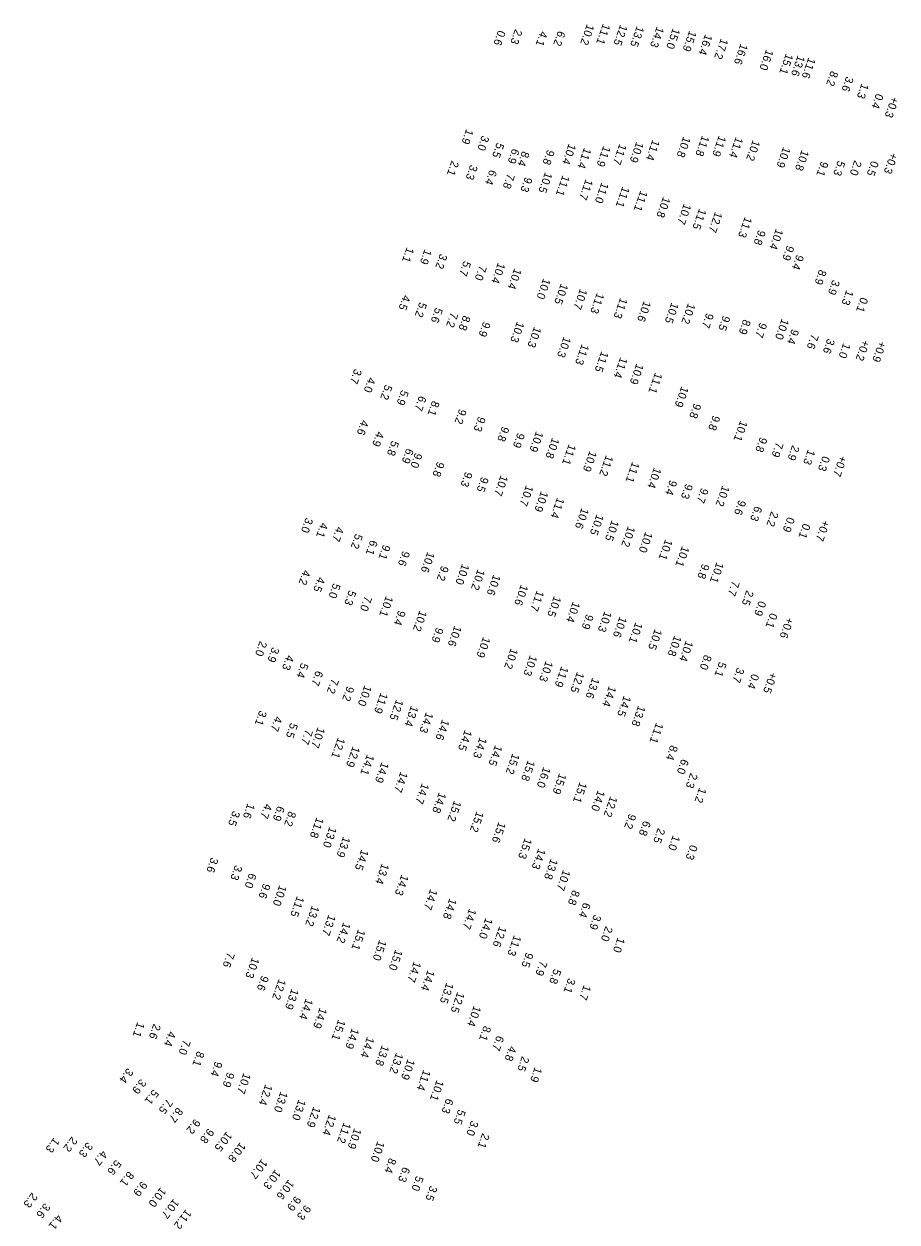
# Model space of a CAD drawing. Extents: x 815385 to 820851, y 582449 to 604245.
# Drawn here: x 817864 to 818409, y 602062 to 602810 of the extents above; entities that cross this region are included whole.
import ezdxf

# ---------------------------------------------------------------- set-up
doc = ezdxf.new("R2010")
doc.units = 0
doc.layers.add('V-TOPO-SOUN-022409', color=7, linetype='Continuous')

msp = doc.modelspace()

# ---------------------------------------------------------------- texts
at = {"layer": 'V-TOPO-SOUN-022409'}
for s, rotation, p in [('10.2 ', 250.57, (818215.18, 602810.48)), ('11.1 ', 250.57, (818225.18, 602810.79)), ('12.5 ', 250.57, (818235.95, 602810.16)), ('0.6', 250.57, (818159.79, 602806.7)), ('2.3', 250.57, (818170.28, 602807.36)), ('4.1', 250.57, (818186.12, 602806.2)), ('6.2', 250.57, (818197.11, 602806.34)), ('13.5 ', 250.57, (818246.32, 602809.31)), ('14.3 ', 250.57, (818258.75, 602808.9)), ('15.0 ', 250.57, (818268.81, 602807.99)), ('15.9 ', 250.57, (818279.06, 602806.41)), ('16.4 ', 250.57, (818288.97, 602804.18)), ('17.2 ', 250.57, (818298.82, 602801.57)), ('16.6 ', 250.57, (818311.09, 602798.29)), ('16.0 ', 250.57, (818327.04, 602794.69)), ('15.1 ', 250.57, (818339.41, 602792.1)), ('13.6 ', 250.57, (818346.74, 602791)), ('11.6 ', 250.57, (818353.41, 602789.58)), ('8.2', 250.57, (818367.48, 602781.33)), ('3.6', 250.57, (818377.07, 602777.89)), ('1.3', 250.57, (818386.62, 602773.44)), ('0.4', 250.57, (818395.7, 602767.21)), ('+0.3 ', 250.57, (818405.31, 602765.25)), ('1.9', 250.57, (818139.8, 602745)), ('3.0', 250.57, (818149.64, 602740.98)), ('5.5', 250.57, (818158.93, 602736.51)), ('10.4 ', 250.57, (818203.82, 602735.82)), ('11.7 ', 250.57, (818235.49, 602735.71)), ('10.9 ', 250.57, (818246.02, 602737.02)), ('11.4 ', 250.57, (818256.12, 602738.3)), ('10.8 ', 250.57, (818275.35, 602740.28)), ('11.8 ', 250.57, (818287.07, 602740.98)), ('11.9 ', 250.57, (818297.53, 602740.83)), ('11.4 ', 250.57, (818308.12, 602740.01)), ('10.2 ', 250.57, (818318.74, 602738.12)), ('6.9', 250.57, (818168.6, 602732.83)), ('8.4', 250.57, (818174.75, 602731.23)), ('9.8', 250.57, (818190.43, 602732.12)), ('11.4 ', 250.57, (818213.39, 602733.31)), ('11.9 ', 250.57, (818225.38, 602734.45)), ('10.9 ', 250.57, (818337.68, 602733.84)), ('10.8 ', 250.57, (818349.24, 602731.93)), ('+0.3 ', 250.57, (818404.69, 602730.21)), ('2.1', 250.57, (818130.69, 602725.27)), ('3.3', 250.57, (818142.41, 602722.72)), ('9.1', 250.57, (818361.36, 602724.91)), ('5.3', 250.57, (818371.84, 602725.28)), ('2.0', 250.57, (818382.17, 602725.47)), ('0.5', 250.57, (818392.74, 602725.2)), ('6.4', 250.57, (818154.44, 602719.6)), ('7.8', 250.57, (818165.54, 602717.17)), ('9.3', 250.57, (818176.58, 602715.08)), ('10.5 ', 250.57, (818189.06, 602718.08)), ('11.1 ', 250.57, (818199.95, 602716.13)), ('11.7 ', 250.57, (818214.39, 602713.68)), ('11.0 ', 250.57, (818224.25, 602711.64)), ('11.1 ', 250.57, (818237.32, 602709.01)), ('11.1 ', 250.57, (818248.55, 602706.56)), ('10.8 ', 250.57, (818262.74, 602702.65)), ('10.7 ', 250.57, (818275.7, 602698.39)), ('11.5 ', 250.57, (818285.2, 602695.26)), ('12.7 ', 250.57, (818295.2, 602693.29)), ('11.3 ', 250.57, (818313.73, 602690.15)), ('10.4 ', 250.57, (818333.17, 602682.71)), ('9.8', 250.57, (818322.18, 602682.01)), ('1.1', 250.57, (818102.68, 602671.16)), ('1.9', 250.57, (818113.82, 602669.91)), ('9.9', 250.57, (818340.02, 602672.3)), ('3.2', 250.57, (818123.49, 602667.15)), ('5.7', 250.57, (818138.24, 602662.62)), ('10.4 ', 250.57, (818159.64, 602661.51)), ('9.4', 250.57, (818346.05, 602666.59)), ('7.0', 250.57, (818148.03, 602659.92)), ('10.4 ', 250.57, (818169.84, 602657.96)), ('8.9', 250.57, (818360.22, 602657.27)), ('10.0 ', 250.57, (818187.91, 602651.78)), ('10.5 ', 250.57, (818198.91, 602648.5)), ('10.7 ', 250.57, (818210.88, 602645.3)), ('3.9', 250.57, (818368.51, 602650.91)), ('4.5', 250.57, (818100.51, 602641.38)), ('11.3 ', 250.57, (818221.42, 602642.69)), ('11.3 ', 250.57, (818235.97, 602639.63)), ('10.6 ', 250.57, (818250.68, 602637.66)), ('1.3', 250.57, (818377.08, 602644.45)), ('0.1', 250.57, (818386.11, 602640)), ('5.2', 250.57, (818110.69, 602636.91)), ('5.6', 250.57, (818120.61, 602633.5)), ('10.5 ', 250.57, (818267.94, 602636.65)), ('10.2 ', 250.57, (818278.31, 602636.24)), ('9.7', 250.57, (818289.74, 602630.16)), ('7.2', 250.57, (818130.23, 602630.57)), ('8.8', 250.57, (818137.97, 602628.63)), ('9.9', 250.57, (818150.43, 602624.71)), ('10.3 ', 250.57, (818171.5, 602624.72)), ('9.5', 250.57, (818300.07, 602628.53)), ('8.9', 250.57, (818312.84, 602626.19)), ('9.7', 250.57, (818323.04, 602624.18)), ('10.0 ', 250.57, (818336.77, 602626.51)), ('10.3 ', 250.57, (818182.19, 602621.54)), ('10.3 ', 250.57, (818200.69, 602615.32)), ('9.4', 250.57, (818343, 602620.12)), ('7.6', 250.57, (818355.31, 602617.08)), ('11.3 ', 250.57, (818211.96, 602610.71)), ('3.6', 250.57, (818365.35, 602614.21)), ('1.0', 250.57, (818375.19, 602611.36)), ('+0.2 ', 250.57, (818387.15, 602613.41)), ('+0.9 ', 250.57, (818397.45, 602612.63)), ('11.5 ', 250.57, (818224.19, 602606.2)), ('11.4 ', 250.57, (818235.99, 602602.51)), ('3.7', 250.57, (818070.07, 602595.3)), ('10.9 ', 250.57, (818246.07, 602598.49)), ('11.1 ', 250.57, (818257.72, 602592.85)), ('4.0', 250.57, (818078.74, 602589.94)), ('5.2', 250.57, (818089.12, 602585.38)), ('5.9', 250.57, (818099.3, 602582.04)), ('6.7', 250.57, (818110.43, 602578.42)), ('10.9 ', 250.57, (818274.13, 602584.29)), ('8.1', 250.57, (818118.64, 602575.37)), ('9.8', 250.57, (818281.95, 602573.77)), ('4.6', 250.57, (818074.43, 602563.34)), ('9.2', 250.57, (818135.48, 602570.23)), ('9.3', 250.57, (818147.35, 602565.51)), ('9.8', 250.57, (818293.8, 602566.25)), ('10.1 ', 250.57, (818310.9, 602562.94)), ('4.9', 250.57, (818084, 602556.19)), ('9.8', 250.57, (818162.14, 602559.31)), ('9.9', 250.57, (818171.82, 602555.34)), ('10.9 ', 250.57, (818183.43, 602556.26)), ('5.8', 250.57, (818093.27, 602550.43)), ('10.8 ', 250.57, (818193.46, 602552.2)), ('11.1 ', 250.57, (818203.85, 602548.18)), ('9.8', 250.57, (818323.22, 602552.63)), ('7.9', 250.57, (818333.31, 602549.5)), ('2.9', 250.57, (818343.33, 602547.51)), ('6.9', 250.57, (818102.48, 602545.6)), ('9.0', 250.57, (818107.85, 602542.82)), ('10.9 ', 250.57, (818216.78, 602544)), ('11.2 ', 250.57, (818227.08, 602541.28)), ('1.3', 250.57, (818353.12, 602544.84)), ('0.3', 250.57, (818362.33, 602540.84)), ('+0.7 ', 250.57, (818372.93, 602541.11)), ('9.8', 250.57, (818121.68, 602537.33)), ('11.1 ', 250.57, (818243.46, 602537.14)), ('10.4 ', 250.57, (818257.06, 602533.64)), ('9.3', 250.57, (818139.2, 602531)), ('9.5', 250.57, (818149.26, 602527.81)), ('10.7 ', 250.57, (818161.37, 602528.83)), ('9.4', 250.57, (818266.91, 602525.85)), ('10.7 ', 250.57, (818177.19, 602522.54)), ('10.9 ', 250.57, (818186.52, 602518.88)), ('9.3', 250.57, (818276.75, 602523.48)), ('9.7', 250.57, (818286.52, 602520.87)), ('10.2 ', 250.57, (818299.68, 602522.33)), ('11.4 ', 250.57, (818196.6, 602514.88)), ('9.6', 250.57, (818309.95, 602513.41)), ('10.6 ', 250.57, (818211.84, 602508.39)), ('10.5 ', 250.57, (818221.19, 602504.39)), ('6.3', 250.57, (818319.97, 602509.6)), ('2.2', 250.57, (818330.2, 602506.23)), ('3.0', 250.57, (818039.62, 602502.32)), ('4.1', 250.57, (818049.06, 602499.31)), ('4.7', 250.57, (818058.9, 602496.78)), ('10.5 ', 250.57, (818230.64, 602500.71)), ('10.2 ', 250.57, (818240.8, 602497.02)), ('0.9', 250.57, (818340.32, 602502.74)), ('0.1', 250.57, (818350.14, 602498.75)), ('+0.7 ', 250.57, (818362.17, 602500.83)), ('5.2', 250.57, (818070.64, 602492.3)), ('6.1', 250.57, (818080.03, 602488.36)), ('10.0 ', 250.57, (818251.65, 602493.43)), ('10.1 ', 250.57, (818264.1, 602488.83)), ('9.1', 250.57, (818087.99, 602485.53)), ('9.6', 250.57, (818100.09, 602481.57)), ('10.6 ', 250.57, (818115.61, 602480.97)), ('10.1 ', 250.57, (818274.54, 602484.58)), ('10.0 ', 250.57, (818137.24, 602473.43)), ('9.8', 250.57, (818287.11, 602473.58)), ('10.1 ', 250.57, (818296.09, 602474.52)), ('4.2', 250.57, (818038.1, 602469.73)), ('4.5', 250.57, (818047.25, 602465.39)), ('9.2', 250.57, (818124.34, 602472.31)), ('10.2 ', 250.57, (818146.97, 602470.05)), ('10.6 ', 250.57, (818156.77, 602466.77)), ('5.0', 250.57, (818056.8, 602461.4)), ('10.6 ', 250.57, (818173.97, 602460.49)), ('7.7', 250.57, (818305.9, 602462.91)), ('5.3', 250.57, (818066.61, 602457.01)), ('7.0', 250.57, (818076.44, 602453.42)), ('10.1 ', 250.57, (818089.7, 602453.44)), ('11.7 ', 250.57, (818183.91, 602456.85)), ('10.5 ', 250.57, (818194.59, 602453.33)), ('2.5', 250.57, (818314.77, 602456.99)), ('9.4', 250.57, (818097.46, 602444.51)), ('10.2 ', 250.57, (818110.72, 602444.3)), ('10.4 ', 250.57, (818206.37, 602449.87)), ('10.3 ', 250.57, (818226.15, 602443.88)), ('0.9', 250.57, (818322.49, 602450.39)), ('9.9', 250.57, (818214.77, 602442.04)), ('10.6 ', 250.57, (818235.58, 602440.51)), ('10.1 ', 250.57, (818245.45, 602436.96)), ('0.1', 250.57, (818329.6, 602442.82)), ('+0.6 ', 250.57, (818339.71, 602440.13)), ('9.9', 250.57, (818121.08, 602433.81)), ('10.6 ', 250.57, (818132.44, 602434.85)), ('10.5 ', 250.57, (818257.52, 602432.78)), ('10.8 ', 250.57, (818269.71, 602428.7)), ('2.0', 250.57, (818010.96, 602425.28)), ('3.9', 250.57, (818018.62, 602421.47)), ('10.9 ', 250.57, (818150.38, 602427.86)), ('10.2 ', 250.57, (818167.66, 602420.78)), ('10.4 ', 250.57, (818276.95, 602425.46)), ('4.3', 250.57, (818027.78, 602416.58)), ('10.3 ', 250.57, (818179.63, 602416.44)), ('8.0', 250.57, (818288.5, 602416.75)), ('5.4', 250.57, (818036.73, 602411.67)), ('6.7', 250.57, (818045.97, 602406.79)), ('10.3 ', 250.57, (818189.49, 602412.83)), ('11.9 ', 250.57, (818199.16, 602409.44)), ('12.5 ', 250.57, (818208.98, 602405.95)), ('5.1', 250.57, (818297.71, 602412.36)), ('3.7', 250.57, (818308.86, 602408.67)), ('7.2', 250.57, (818055.74, 602401.87)), ('13.6 ', 250.57, (818218.52, 602402.34)), ('0.4', 250.57, (818318.14, 602404.84)), ('+0.5 ', 250.57, (818329.37, 602405.81)), ('9.2', 250.57, (818065.33, 602397.12)), ('10.0 ', 250.57, (818076.3, 602397.6)), ('11.9 ', 250.57, (818086.42, 602392.98)), ('14.4 ', 250.57, (818228.93, 602397.23)), ('14.5 ', 250.57, (818238.21, 602391.13)), ('12.5 ', 250.57, (818096.1, 602388.8)), ('13.4 ', 250.57, (818105.39, 602384.85)), ('13.8 ', 250.57, (818247.18, 602384.97)), ('3.1', 250.57, (818010.77, 602381.93)), ('4.7', 250.57, (818020.56, 602378.32)), ('14.3 ', 250.57, (818114.74, 602380.83)), ('14.6 ', 250.57, (818124.8, 602376.36)), ('5.5', 250.57, (818030.14, 602374.17)), ('7.7', 250.57, (818039.51, 602370.14)), ('10.7 ', 250.57, (818047.11, 602371.44)), ('14.5 ', 250.57, (818138.89, 602369.71)), ('11.1 ', 250.57, (818258.38, 602374.27)), ('12.1 ', 250.57, (818059.73, 602364.99)), ('14.3 ', 250.57, (818148.22, 602365.08)), ('12.9 ', 250.57, (818068.97, 602359.49)), ('14.1 ', 250.57, (818077.89, 602354.47)), ('14.5 ', 250.57, (818157.85, 602360.3)), ('15.2 ', 250.57, (818168.65, 602355.07)), ('8.4', 250.57, (818267.34, 602360.31)), ('14.9 ', 250.57, (818086.99, 602349.65)), ('15.8 ', 250.57, (818178.28, 602350.82)), ('16.0 ', 250.57, (818188.01, 602346.64)), ('6.0', 250.57, (818274.22, 602351.64)), ('14.7 ', 250.57, (818098.82, 602343.67)), ('15.9 ', 250.57, (818197.87, 602342.61)), ('2.3', 250.57, (818279.76, 602342.84)), ('14.7 ', 250.57, (818112.16, 602336.44)), ('14.8 ', 250.57, (818122.8, 602330.77)), ('15.1 ', 250.57, (818210.66, 602337.16)), ('14.0 ', 250.57, (818221.96, 602332.08)), ('1.2', 250.57, (818285.26, 602333.66)), ('1.6', 250.57, (818003.34, 602323.89)), ('4.7', 250.57, (818014.13, 602323.79)), ('15.2 ', 250.57, (818132.25, 602325.58)), ('12.2 ', 250.57, (818229.74, 602328.32)), ('3.5', 250.57, (817994.07, 602319.23)), ('6.9', 250.57, (818021.95, 602322.32)), ('8.2', 250.57, (818029.07, 602318.99)), ('15.2 ', 250.57, (818146.27, 602318.88)), ('9.2', 250.57, (818241.38, 602317.37)), ('11.8 ', 250.57, (818046.39, 602315.18)), ('13.0 ', 250.57, (818054.47, 602309.23)), ('15.6 ', 250.57, (818159.99, 602312.26)), ('6.8', 250.57, (818250.49, 602313.09)), ('2.5', 250.57, (818259.47, 602308.48)), ('13.9 ', 250.57, (818062.99, 602303.14)), ('15.3 ', 250.57, (818176.38, 602302.19)), ('1.0', 250.57, (818268.81, 602303.97)), ('14.5 ', 250.57, (818074.39, 602295.08)), ('14.3 ', 250.57, (818184.81, 602295.68)), ('0.3', 250.57, (818279.71, 602298.06)), ('3.6', 250.57, (817980.53, 602290.13)), ('13.4 ', 250.57, (818087.17, 602286.37)), ('13.8 ', 250.57, (818192.59, 602289.28)), ('3.3', 250.57, (817995.51, 602285.38)), ('6.0', 250.57, (818004.39, 602280.4)), ('14.3 ', 250.57, (818099.39, 602279.36)), ('10.7 ', 250.57, (818200.3, 602282.4)), ('9.6', 250.57, (818013.09, 602273.92)), ('10.0 ', 250.57, (818023.2, 602272.8)), ('11.5 ', 250.57, (818034.15, 602265.97)), ('14.7 ', 250.57, (818117.4, 602270.37)), ('14.8 ', 250.57, (818129.39, 602264.61)), ('8.8', 250.57, (818206.2, 602269.78)), ('13.2 ', 250.57, (818043.53, 602260.08)), ('14.7 ', 250.57, (818141.65, 602258.22)), ('6.4', 250.57, (818212.96, 602262)), ('13.7 ', 250.57, (818053.85, 602254.32)), ('14.2 ', 250.57, (818063.08, 602249.62)), ('14.0 ', 250.57, (818151.85, 602252.34)), ('3.9', 250.57, (818219.57, 602254.44)), ('15.1 ', 250.57, (818072.32, 602245.22)), ('12.6 ', 250.57, (818160.51, 602247.15)), ('11.3 ', 250.57, (818169.67, 602241.59)), ('2.0', 250.57, (818226.78, 602247.18)), ('15.0 ', 250.57, (818085.57, 602238.66)), ('1.0', 250.57, (818234.36, 602240.15)), ('7.6', 250.57, (817990.71, 602230.91)), ('10.3 ', 250.57, (818006.13, 602227.67)), ('15.0 ', 250.57, (818095.58, 602232.58)), ('9.5', 250.57, (818177.2, 602230.86)), ('14.7 ', 250.57, (818107.16, 602225.15)), ('14.4 ', 250.57, (818115.72, 602219.83)), ('7.9', 250.57, (818185.91, 602225.67)), ('5.8', 250.57, (818194.55, 602220.57)), ('9.6', 250.57, (818012.02, 602216.4)), ('12.2 ', 250.57, (818022.83, 602214.23)), ('13.5 ', 250.57, (818127.46, 602211.88)), ('3.1', 250.57, (818203.5, 602214.77)), ('13.9 ', 250.57, (818030.78, 602208.12)), ('12.5 ', 250.57, (818134.27, 602206.05)), ('1.7', 250.57, (818213.21, 602210.49)), ('14.4 ', 250.57, (818039.66, 602201.95)), ('14.9 ', 250.57, (818048.38, 602196.27)), ('10.4 ', 250.57, (818144.58, 602197.5)), ('15.1 ', 250.57, (818059.92, 602188.88)), ('1.1', 250.57, (817934.53, 602187.34)), ('2.6', 250.57, (817944.62, 602186.22)), ('4.4', 250.57, (817954.01, 602181.64)), ('14.9 ', 250.57, (818068.44, 602183.51)), ('8.1', 250.57, (818150.77, 602184.98)), ('7.0', 250.57, (817963.18, 602176.35)), ('14.4 ', 250.57, (818077.94, 602178.05)), ('6.7', 250.57, (818158.88, 602178.87)), ('8.1', 250.57, (817971.85, 602169.13)), ('13.8 ', 250.57, (818087.19, 602172.89)), ('13.2 ', 250.57, (818096.02, 602168.12)), ('4.8', 250.57, (818166.74, 602172.38)), ('2.5', 250.57, (818174.63, 602165.94)), ('9.4', 250.57, (817983.07, 602162.83)), ('10.9 ', 250.57, (818103.26, 602164.21)), ('1.9', 250.57, (818182.63, 602159.2)), ('3.4', 232.428, (817928.48, 602158.63)), ('3.9', 232.428, (817936.56, 602151.88)), ('9.9', 250.57, (817990.62, 602156.06)), ('10.7 ', 250.57, (818000.82, 602155.52)), ('11.4 ', 250.57, (818113.07, 602157.5)), ('10.1 ', 250.57, (818121.34, 602151.11)), ('5.1', 232.428, (817944.37, 602145.24)), ('12.4 ', 250.57, (818014.38, 602148.37)), ('13.0 ', 250.57, (818023.91, 602143.97)), ('7.5', 232.428, (817953.08, 602139.43)), ('13.0 ', 250.57, (818035.17, 602138.96)), ('6.3', 250.57, (818127.35, 602139.66)), ('8.7', 232.428, (817959.48, 602134.06)), ('12.9 ', 250.57, (818044.4, 602134.5)), ('12.4 ', 250.57, (818054.16, 602129.52)), ('5.5', 250.57, (818134.91, 602132.8)), ('9.2', 232.428, (817970.42, 602126.92)), ('11.2 ', 250.57, (818063.34, 602124.61)), ('3.0', 250.57, (818142.83, 602125.76)), ('1.3', 232.428, (817882.52, 602115.16)), ('2.2', 232.428, (817893.6, 602115.75)), ('9.8', 232.428, (817978.87, 602121)), ('10.5 ', 232.428, (817990.2, 602118.95)), ('10.9 ', 250.57, (818069.91, 602121.07)), ('2.1', 250.57, (818149.84, 602117.89)), ('3.3', 232.428, (817903.25, 602112.35)), ('4.7', 232.428, (817912.42, 602107.26)), ('10.8 ', 232.428, (817998.67, 602112.23)), ('10.0 ', 250.57, (818084.39, 602112.91)), ('5.6', 232.428, (817921.01, 602101.33)), ('10.7 ', 232.428, (818012.18, 602101.78)), ('8.4', 250.57, (818091.63, 602102.46)), ('8.1', 232.428, (817928.9, 602094.17)), ('10.3 ', 232.428, (818020.66, 602095.29)), ('6.3', 250.57, (818100.21, 602096.88)), ('9.9', 232.428, (817937.2, 602087.97)), ('10.0 ', 232.428, (817949.04, 602084.17)), ('10.6 ', 232.428, (818028.87, 602088.93)), ('5.0', 250.57, (818108.58, 602091.29)), ('3.5', 250.57, (818117.25, 602085.13)), ('2.3', 232.428, (817868.74, 602080.82)), ('10.7 ', 232.428, (817957.11, 602077)), ('9.9', 232.428, (818033.19, 602078.78)), ('3.6', 232.428, (817876.71, 602074.32)), ('11.2 ', 232.428, (817964.87, 602070.43)), ('9.3', 232.428, (818039.38, 602073.19)), ('4.1', 232.428, (817884.4, 602067.21))]:
    msp.add_text(s, height=5, rotation=rotation, dxfattribs=at).set_placement(p)

doc.saveas('drawing.dxf')
